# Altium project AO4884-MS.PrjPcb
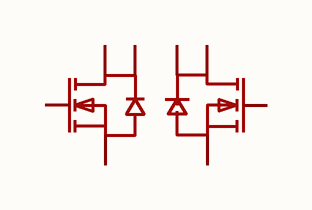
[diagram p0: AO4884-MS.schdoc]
1 sheet, 1 parts. Net scope: global (net labels, ports and power ports of the same name join across sheets).

## Sheet AO4884-MS.schdoc
size 127 x 101 mm

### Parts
Q?  ao4884-ms  [SOP-8_L4.9-W3.9-P1.27-LS6.0-BL]  (value not drawn)

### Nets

Not connected (* = marked no-connect by the designer): Q? 1(S1) 2(G1) 3(S2) 4(G2) 5(D2) 6(D2) 7(D1) 8(D1)

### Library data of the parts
Q? = ao4884-ms: 数量:2个N沟道;漏源电压(Vdss):40V;连续漏极电流(Id):10A;导通电阻(RDS(on)):20mΩ@10V;耗散功率(Pd):2W;阈值电压(Vgs(th)):2V;; Manufacturer: MSKSEMI(美森科); AddInBom: yes; ModelId: 75c24a7891ee4dd6bdac16a7163ff87e; ModelName: SOP-8_L4.9-W3.9-P1.27-LS6.0-BL-1; ModelTransform: 192.913,236.22,0,0,0,0,-0.393,2.749,0; Number: 2个N沟道; Drain to Source Voltage: 40V; Current - Continuous Drain(Id): 10A; Pd - Power Dissipation: 2W; Gate Threshold Voltage (Vgs(th)): 2V; Gate Charge(Qg): 22.9nC@10V; Input Capacitance(Ciss): 964pF; Reverse Transfer Capacitance (Crss@Vds): 96pF; Type: N沟道; Output Capacitance(Coss): 109pF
